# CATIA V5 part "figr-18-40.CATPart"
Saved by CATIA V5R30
Part number: Part1
Bounding box of the stored display mesh (mm): x -198 to 20, y -85 to 85, z 0 to 0
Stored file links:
  D:\PROJECTS\CATIA V56R 2020\Resources\Parts File\c18_catia_v6_6r2020_prt\figr-18-40.CATPart
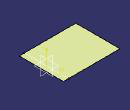
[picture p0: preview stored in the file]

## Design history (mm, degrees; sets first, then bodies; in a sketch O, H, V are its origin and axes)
Body1 (main body)
  Sketch1 on yz-plane, origin (0, 0, 0), H (0, 1, 0), V (0, 0, 1)
    line L1 (-85, 0) -> (85, 0)
    point P1 (-85, 0)
    coincidence: P1 H
    horizontal: L1 H
  Extrude1: Element1 Sketch1, Lim1 20, Lim2 198
  DatumSurface1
